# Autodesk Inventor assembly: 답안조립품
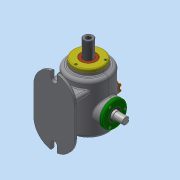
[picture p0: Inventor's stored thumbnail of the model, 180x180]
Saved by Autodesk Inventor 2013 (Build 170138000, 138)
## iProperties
Created: 2018-02
Part Number: 답안조립품
Document SubType Name: Assembly
Designer: dgall
Author: dgall
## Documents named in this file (16)
- C:\Users\dgall\Desktop\380207V1013\답안조립품.iam
- C:\Users\dgall\Desktop\380207V1013\본체.ipt
- C:\Users\dgall\Desktop\380207V1013\베어링 6205.ipt
- 베어링 6205.ipt
- C:\Users\dgall\Desktop\380207V1013\오일실.ipt
- 오일실.ipt
- C:\Users\dgall\Desktop\380207V1013\축 커버-1.ipt
- C:\Users\dgall\Desktop\380207V1013\편심축.ipt
- C:\Users\dgall\Desktop\380207V1013\축 커버-2.ipt
- C:\Users\dgall\Desktop\380207V1013\가변스프링.ipt
- C:\Users\dgall\Desktop\380207V1013\부시.ipt
- C:\Users\dgall\Desktop\380207V1013\슬라이드 커버.ipt
- C:\Users\dgall\Desktop\380207V1013\슬라이드.ipt
- C:\Users\dgall\Desktop\380207V1013\본체커버.ipt
- C:\Users\dgall\Desktop\380207V1013\상부 캡.ipt
- C:\Users\dgall\Desktop\380207V1013\볼트 M4.ipt
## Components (1 placed, 1 different names)
1. 가변스프링:1
